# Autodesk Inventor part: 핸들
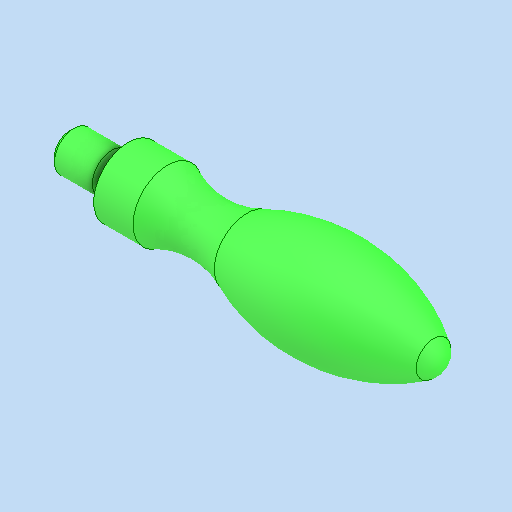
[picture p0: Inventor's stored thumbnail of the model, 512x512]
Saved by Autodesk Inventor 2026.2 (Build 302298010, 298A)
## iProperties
Created: 2026-08
Part Number: 핸들
Material: 스테인리스강
Document SubType Name: Modeling
Designer: PC2-02
Density: 8.08 g/cm^3
Appearance: 기본값
Author: jhkim
Sending System: Autodesk Inventor 2027
Preprocessor: ST-DEVELOPER v20.1
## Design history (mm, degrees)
feature "솔리드1"
node "솔리드2"
